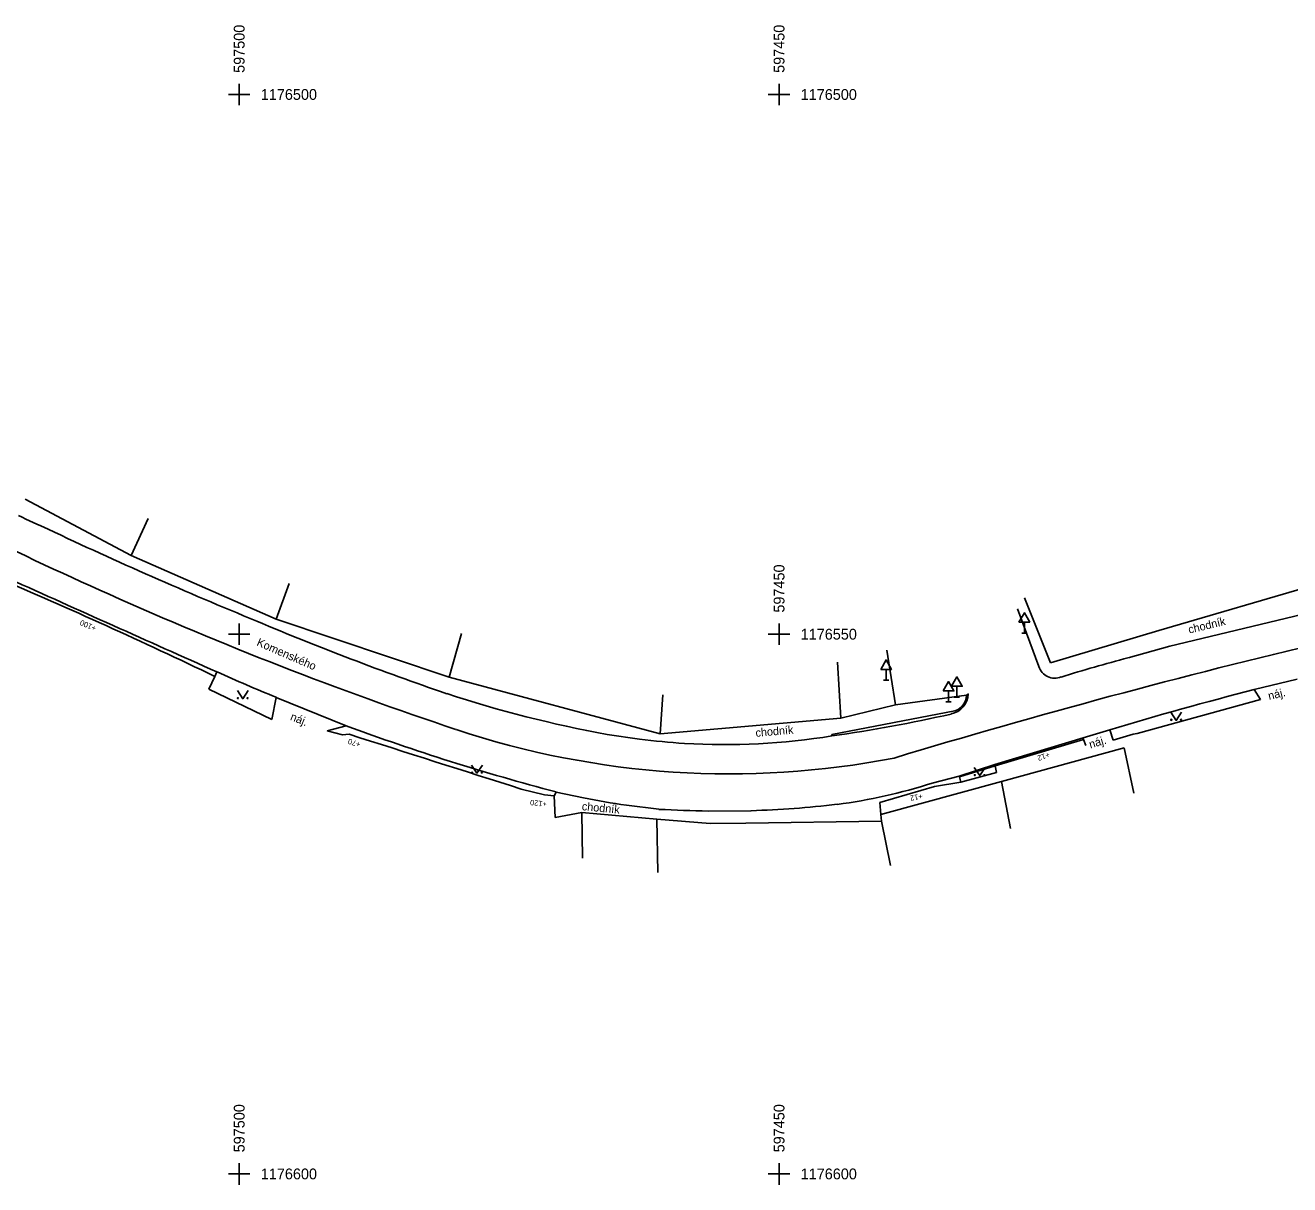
# Model space of a CAD drawing. Extents: x -598160 to -596067, y -1177005 to -1176344.
# Drawn here: x -597519.8 to -597402.7, y -1176601 to -1176493.6 of the extents above; entities that cross this region are included whole.
import ezdxf

# ---------------------------------------------------------------- set-up
doc = ezdxf.new("R2010")
doc.units = 0
for name, color, linetype in [('budova', 7, 'Continuous'), ('dopravní značení svislé', 7, 'Continuous'), ('hektametrová síť', 7, 'Continuous'), ('obruba +0 cm', 7, 'Continuous'), ('obruba +12 cm', 7, 'Continuous'), ('ohradní zeď', 7, 'Continuous'), ('plot', 7, 'Continuous'), ('popis ploch', 7, 'Continuous'), ('rozhraní ploch', 7, 'Continuous'), ('vodorovné značení', 7, 'Continuous'), ('výška stupně', 7, 'Continuous'), ('zeleň', 7, 'Continuous')]:
    doc.layers.add(name, color=color, linetype=linetype)

msp = doc.modelspace()

# ---------------------------------------------------------------- linework, layer by layer
at = {"layer": 'budova'}
for p, q in [((-597510, -1176542.72), (-597508.42, -1176539.29)), ((-597510, -1176542.72), (-597496.58, -1176548.6)), ((-597496.58, -1176548.6), (-597495.38, -1176545.3)), ((-597414.83, -1176549.67), (-597399.45, -1176545.15)), ((-597427.28, -1176546.62), (-597424.86, -1176552.64)), ((-597496.58, -1176548.6), (-597480.55, -1176553.99)), ((-597424.86, -1176552.64), (-597414.83, -1176549.67)), ((-597480.55, -1176553.99), (-597479.41, -1176549.95)), ((-597444.29, -1176557.78), (-597444.58, -1176552.6)), ((-597480.55, -1176553.99), (-597461, -1176559.22)), ((-597461, -1176559.22), (-597460.75, -1176555.61)), ((-597461, -1176559.22), (-597444.29, -1176557.78)), ((-597429.39, -1176563.66), (-597418.03, -1176560.54)), ((-597418.03, -1176560.54), (-597417.13, -1176564.74)), ((-597440.56, -1176566.71), (-597429.39, -1176563.66)), ((-597429.39, -1176563.66), (-597428.56, -1176567.99)), ((-597470.73, -1176566.98), (-597468.28, -1176566.51)), ((-597468.28, -1176566.51), (-597461.33, -1176567.15)), ((-597468.28, -1176566.51), (-597468.22, -1176570.76)), ((-597461.33, -1176567.15), (-597456.39, -1176567.54)), ((-597461.33, -1176567.15), (-597461.23, -1176572.07)), ((-597440.52, -1176567.32), (-597440.56, -1176566.71)), ((-597456.39, -1176567.54), (-597453.09, -1176567.5)), ((-597453.09, -1176567.5), (-597440.52, -1176567.32)), ((-597440.52, -1176567.32), (-597439.67, -1176571.44))]:
    msp.add_line(p, q, dxfattribs=at)
at = {"layer": 'dopravní značení svislé'}
for p, q in [((-597427.28, -1176548.88), (-597427.28, -1176549.89)), ((-597427.53, -1176549.89), (-597427.03, -1176549.89)), ((-597440.34, -1176554.27), (-597439.84, -1176554.27)), ((-597440.09, -1176553.26), (-597440.09, -1176554.27)), ((-597434.31, -1176555.26), (-597434.31, -1176556.27)), ((-597433.53, -1176554.82), (-597433.53, -1176555.83)), ((-597434.56, -1176556.27), (-597434.06, -1176556.27)), ((-597433.78, -1176555.83), (-597433.28, -1176555.83))]:
    msp.add_line(p, q, dxfattribs=at)
for points in [[(-597427.78, -1176548.88), (-597426.78, -1176548.88), (-597427.28, -1176548.01)], [(-597440.59, -1176553.26), (-597439.59, -1176553.26), (-597440.09, -1176552.39)], [(-597434.81, -1176555.26), (-597433.81, -1176555.26), (-597434.31, -1176554.39)], [(-597434.03, -1176554.82), (-597433.03, -1176554.82), (-597433.53, -1176553.95)]]:
    msp.add_lwpolyline(points, close=True, dxfattribs=at)
at = {"layer": 'hektametrová síť'}
for p, q in [((-597500, -1176501), (-597500, -1176499)), ((-597450, -1176501), (-597450, -1176499)), ((-597501, -1176500), (-597499, -1176500)), ((-597451, -1176500), (-597449, -1176500)), ((-597500, -1176551), (-597500, -1176549)), ((-597450, -1176551), (-597450, -1176549)), ((-597501, -1176550), (-597499, -1176550)), ((-597451, -1176550), (-597449, -1176550)), ((-597501, -1176600), (-597499, -1176600)), ((-597500, -1176601), (-597500, -1176599)), ((-597451, -1176600), (-597449, -1176600)), ((-597450, -1176601), (-597450, -1176599))]:
    msp.add_line(p, q, dxfattribs=at)
at = {"layer": 'obruba +0 cm'}
for p, q in [((-597417.68, -1176552.19), (-597413.8, -1176551.1)), ((-597405.99, -1176555.13), (-597402.01, -1176554.16)), ((-597496.58, -1176555.85), (-597490.1, -1176558.49)), ((-597421.84, -1176559.59), (-597419.36, -1176558.85)), ((-597465.93, -1176559.29), (-597462.92, -1176559.72)), ((-597435.82, -1176563.79), (-597433.33, -1176563.14)), ((-597470.64, -1176564.62), (-597468.11, -1176565.15)), ((-597464.14, -1176565.85), (-597461.12, -1176566.22)), ((-597456.56, -1176566.38), (-597452.6, -1176566.35))]:
    msp.add_line(p, q, dxfattribs=at)
msp.add_arc((-597242.16, -1175937.85), 662.45, 245.15933, 245.4221, dxfattribs=at)
at = {"layer": 'obruba +12 cm'}
for p, q in [((-597425.93, -1176552.99), (-597427.91, -1176547.64)), ((-597399.01, -1176547.56), (-597413.8, -1176551.1)), ((-597421.84, -1176559.59), (-597430.01, -1176562.08)), ((-597430.01, -1176562.08), (-597433.33, -1176563.14))]:
    msp.add_line(p, q, dxfattribs=at)
for centre, radius, start, end in [((-597350.75, -1176187.47), 390.31, 244.678, 247.7773), ((-595960.58, -1173088.91), 3792.03, 245.69611, 246.01452), ((-597390.46, -1176292.7), 277.9, 247.1499, 251.0329), ((-597424.47, -1176552.56), 1.52, 196.2878, 292.612), ((-597376.12, -1176708.65), 161.89, 104.8771, 107.1601), ((-597445.09, -1176428.76), 137.12, 245.4539, 247.9472), ((-597445.21, -1176446.81), 114.37, 251.8778, 259.56), ((-597434.47, -1176555.43), 2, 281.8418, 357.108), ((-597320.18, -1176889.41), 345.12, 104.3964, 106.7005), ((-597465.2, -1176419.09), 141.77, 278.15, 282.6879), ((-597417.53, -1176362.06), 209.4, 249.723, 255.3076), ((-597454.93, -1176496.93), 63.3, 262.7528, 266.5355), ((-597454.97, -1176499.57), 60.66, 266.4181, 279.3652), ((-597450.63, -1176518.25), 47.89, 277.196, 288.0131), ((-597454.46, -1176499.33), 67.22, 258.2821, 261.7184), ((-597455.26, -1176476.26), 90.13, 271.6928, 276.7747), ((-597452.74, -1176392.45), 173.98, 267.2391, 268.7418)]:
    msp.add_arc(centre, radius, start, end, dxfattribs=at)
at = {"layer": 'ohradní zeď'}
for p, q in [((-597502.25, -1176553.91), (-597502.81, -1176555.08)), ((-597502.25, -1176553.91), (-597502.81, -1176555.08)), ((-597490.44, -1176559.32), (-597491.86, -1176558.95)), ((-597489.82, -1176559.27), (-597490.44, -1176559.32)), ((-597471.71, -1176564.88), (-597473.87, -1176564.35)), ((-597470.84, -1176564.96), (-597471.71, -1176564.88))]:
    msp.add_line(p, q, dxfattribs=at)
for centre, radius, start, end in [((-597741.74, -1177054.96), 555.35, 64.4531, 66.7485), ((-595093.47, -1169062.87), 7870.1, 252.272634, 252.3945)]:
    msp.add_arc(centre, radius, start, end, dxfattribs=at)
at = {"layer": 'plot'}
msp.add_line((-597519.81, -1176537.49), (-597510, -1176542.72), dxfattribs=at)
at = {"layer": 'rozhraní ploch'}
for p, q in [((-597440.01, -1176551.48), (-597439.22, -1176556.54)), ((-597502.25, -1176553.91), (-597502.06, -1176553.49)), ((-597502.81, -1176555.08), (-597496.99, -1176557.89)), ((-597432.64, -1176555.66), (-597432.47, -1176555.53)), ((-597405.4, -1176556.06), (-597405.99, -1176555.13)), ((-597496.99, -1176557.89), (-597496.58, -1176555.85)), ((-597444.29, -1176557.78), (-597439.22, -1176556.54)), ((-597439.22, -1176556.54), (-597432.64, -1176555.66)), ((-597416.85, -1176559.21), (-597405.4, -1176556.06)), ((-597445.12, -1176559.3), (-597433.71, -1176557.1)), ((-597490.1, -1176558.49), (-597491.86, -1176558.95)), ((-597419.36, -1176558.85), (-597419.07, -1176559.81)), ((-597445.1, -1176559.42), (-597445.12, -1176559.3)), ((-597429.98, -1176562.2), (-597421.8, -1176559.75)), ((-597421.84, -1176559.59), (-597421.8, -1176559.75)), ((-597421.8, -1176559.75), (-597421.6, -1176560.32)), ((-597419.07, -1176559.81), (-597417.2, -1176559.27)), ((-597417.2, -1176559.27), (-597416.85, -1176559.21)), ((-597429.98, -1176562.2), (-597433.28, -1176563.21)), ((-597430.01, -1176562.08), (-597429.98, -1176562.2)), ((-597429.85, -1176562.81), (-597429.98, -1176562.2)), ((-597435.6, -1176564.11), (-597433.18, -1176563.7)), ((-597433.33, -1176563.14), (-597433.28, -1176563.21)), ((-597433.28, -1176563.21), (-597433.18, -1176563.7)), ((-597433.18, -1176563.7), (-597429.85, -1176562.81)), ((-597470.84, -1176564.96), (-597470.64, -1176564.62)), ((-597440.68, -1176565.58), (-597435.6, -1176564.11)), ((-597470.84, -1176564.96), (-597470.73, -1176566.98)), ((-597440.56, -1176566.71), (-597440.68, -1176565.58))]:
    msp.add_line(p, q, dxfattribs=at)
msp.add_arc((-597434.15, -1176555.65), 1.51, 286.9842, 359.787, dxfattribs=at)
at = {"layer": 'vodorovné značení'}
for centre, radius, start, end in [((-597409.37, -1176311.99), 255.81, 239.5638, 246.3401), ((-597371.14, -1176232.39), 344.08, 245.828, 251.5694), ((-597244.4, -1177206.12), 673.48, 103.28407, 106.82529), ((-597454.58, -1176482.85), 80.09, 251.5561, 280.9713)]:
    msp.add_arc(centre, radius, start, end, dxfattribs=at)
at = {"layer": 'zeleň'}
for points in [[(-597500.17, -1176555.23), (-597499.67, -1176555.98), (-597499.17, -1176555.23)], [(-597413.72, -1176557.23), (-597413.22, -1176557.98), (-597412.72, -1176557.23)], [(-597478.48, -1176562.12), (-597477.98, -1176562.87), (-597477.48, -1176562.12)], [(-597431.92, -1176562.35), (-597431.42, -1176563.1), (-597430.92, -1176562.35)]]:
    msp.add_lwpolyline(points, dxfattribs=at)
for centre in [(-597500.12, -1176555.93), (-597499.22, -1176555.93), (-597413.67, -1176557.93), (-597412.78, -1176557.93), (-597478.43, -1176562.82), (-597477.53, -1176562.82), (-597431.87, -1176563.05), (-597430.97, -1176563.05)]:
    msp.add_circle(centre, 0.05, dxfattribs=at)

# ---------------------------------------------------------------- texts
at = {"layer": 'hektametrová síť'}
for s, p in [('597500', (-597499.5, -1176498)), ('597450', (-597449.5, -1176498)), ('597450', (-597449.5, -1176548)), ('597500', (-597499.5, -1176598)), ('597450', (-597449.5, -1176598))]:
    msp.add_text(s, height=1, rotation=90, dxfattribs=at).set_placement(p)
for s, p in [('1176500', (-597498, -1176500.5)), ('1176500', (-597448, -1176500.5)), ('1176550', (-597448, -1176550.5)), ('1176600', (-597498, -1176600.5)), ('1176600', (-597448, -1176600.5))]:
    msp.add_text(s, height=1, dxfattribs=at).set_placement(p)
at = {"layer": 'popis ploch'}
for s, rotation, p in [('chodník', 13.4606, (-597412.01, -1176549.95)), ('Komenského', 336.4477, (-597498.44, -1176551.02)), ('náj.', 13.697, (-597404.61, -1176556.1)), ('náj.', 337.8337, (-597495.33, -1176557.92)), ('chodník', 4.893, (-597452.15, -1176559.51)), ('náj.', 16.6144, (-597421.17, -1176560.59)), ('chodník', 354.7387, (-597468.29, -1176566.3))]:
    msp.add_text(s, height=0.75, rotation=rotation, dxfattribs=at).set_placement(p)
at = {"layer": 'výška stupně'}
for s, rotation, p in [('+100', 156.2505, (-597513.19, -1176549.28)), ('+70', 161.9166, (-597488.71, -1176560.02)), ('+12', 198.8384, (-597425.02, -1176560.9)), ('+12', 190.5948, (-597436.75, -1176564.75)), ('+120', 173.4882, (-597471.48, -1176565.51))]:
    msp.add_text(s, height=0.5, rotation=rotation, dxfattribs=at).set_placement(p)

doc.saveas('drawing.dxf')
